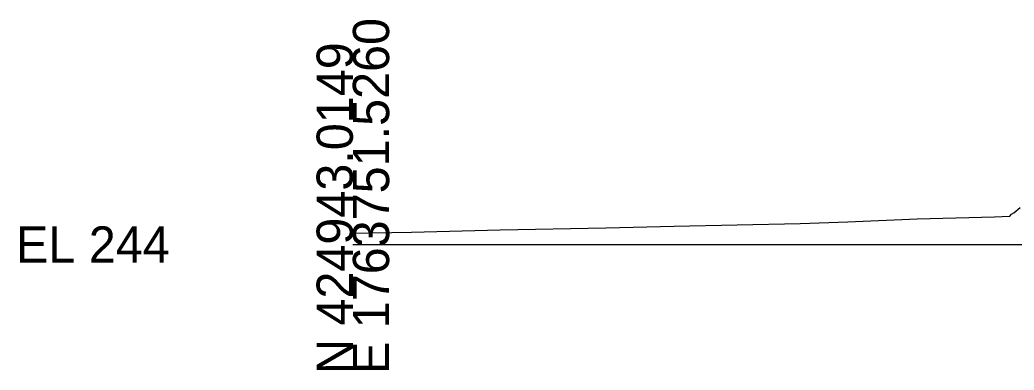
# Model space of a CAD drawing. Extents: x -26 to 3203, y -11010 to 4024.
# Drawn here: x 2974.3 to 3051, y -5509.7 to -5482.7 of the extents above; entities that cross this region are included whole.
import ezdxf

# ---------------------------------------------------------------- set-up
doc = ezdxf.new("R2010")
doc.units = 0
for name, color, linetype in [('Default', 7, 'Continuous'), ('Exist Cross Section Cell', 7, 'Continuous'), ('Exist XS Ground Line', 7, 'Continuous')]:
    doc.layers.add(name, color=color, linetype=linetype)

msp = doc.modelspace()

# ---------------------------------------------------------------- linework, layer by layer
at = {"layer": 'Exist Cross Section Cell'}
msp.add_line((3000, -5500), (3100, -5500), dxfattribs=at)
at = {"layer": 'Exist XS Ground Line'}
msp.add_lwpolyline([(3000, -5499.114), (3004.522, -5499.038), (3011.37, -5498.878), (3019.521, -5498.718), (3024.787, -5498.573), (3034.52, -5498.373), (3038.204, -5498.246), (3043.547, -5498.02), (3049.519, -5497.863), (3050.697, -5497.822), (3050.809, -5497.65), (3050.988, -5497.563), (3051.486, -5497.132)], dxfattribs=at)
msp.add_lwpolyline([(3000, -5499.114), (3004.522, -5499.038), (3011.37, -5498.878), (3019.521, -5498.718), (3024.787, -5498.573), (3034.52, -5498.373), (3038.204, -5498.246), (3043.547, -5498.02), (3049.519, -5497.863), (3050.697, -5497.822), (3050.809, -5497.65), (3050.988, -5497.563), (3051.486, -5497.132)], dxfattribs=at)
msp.add_lwpolyline([(3000, -5499.114), (3004.522, -5499.038), (3011.37, -5498.878), (3019.521, -5498.718), (3024.787, -5498.573), (3034.52, -5498.373), (3038.204, -5498.246), (3043.547, -5498.02), (3049.519, -5497.863), (3050.697, -5497.822), (3050.809, -5497.65), (3050.988, -5497.563), (3051.486, -5497.132)], dxfattribs=at)
msp.add_lwpolyline([(3000, -5499.114), (3004.522, -5499.038), (3011.37, -5498.878), (3019.521, -5498.718), (3024.787, -5498.573), (3034.52, -5498.373), (3038.204, -5498.246), (3043.547, -5498.02), (3049.519, -5497.863), (3050.697, -5497.822), (3050.809, -5497.65), (3050.988, -5497.563), (3051.486, -5497.132)], dxfattribs=at)
msp.add_lwpolyline([(3000, -5499.114), (3004.522, -5499.038), (3011.37, -5498.878), (3019.521, -5498.718), (3024.787, -5498.573), (3034.52, -5498.373), (3038.204, -5498.246), (3043.547, -5498.02), (3049.519, -5497.863), (3050.697, -5497.822), (3050.809, -5497.65), (3050.988, -5497.563), (3051.486, -5497.132)], dxfattribs=at)

# ---------------------------------------------------------------- texts
at = {"layer": 'Default'}
msp.add_text('-', height=0.0001, dxfattribs=at).set_placement((3000, -5500))
at = {"layer": 'Exist Cross Section Cell'}
for s, p in [('E 1763751.5260', (3002.8, -5510)), ('N 424943.0149', (3000, -5510))]:
    msp.add_text(s, height=2.8, rotation=90, dxfattribs=at).set_placement(p)
msp.add_text('EL 244', height=2.8, dxfattribs=at).set_placement((2974, -5501.4))

doc.saveas('drawing.dxf')
